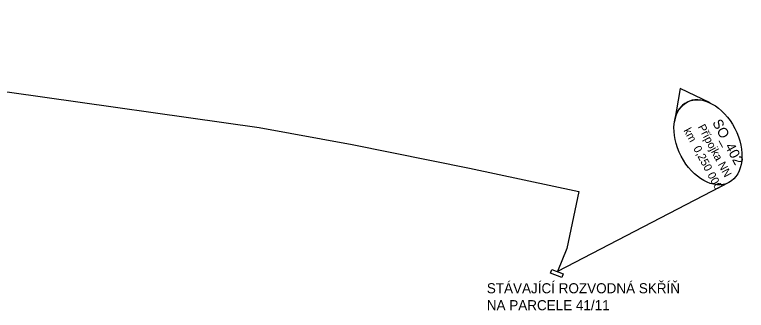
# Model space of a CAD drawing. Extents: x -743359 to -742769, y -1127804 to -1126284.
# Drawn here: x -743077.7 to -742896.2, y -1127156 to -1127082.6 of the extents above; entities that cross this region are included whole.
import ezdxf

# ---------------------------------------------------------------- set-up
doc = ezdxf.new("R2010")
doc.units = 0
for name, color, linetype in [('_Násyp', 7, 'Continuous'), ('_TRASA_vedení kabelu_CEZ', 7, 'Continuous'), ('bublina_růžová_230_čára_tenká', 7, 'Continuous'), ('bublina_růžová_230_čára_tučná', 7, 'Continuous')]:
    doc.layers.add(name, color=color, linetype=linetype)

msp = doc.modelspace()

# ---------------------------------------------------------------- linework, layer by layer
at = {"layer": '_TRASA_vedení kabelu_CEZ'}
msp.add_lwpolyline([(-743154.26, -1127082.61), (-743159.25, -1127091.79), (-743078.98, -1127101.9), (-743017.04, -1127110.61), (-742993.93, -1127114.82), (-742964.82, -1127120.76), (-742937.74, -1127126.54), (-742940.65, -1127140.7), (-742943, -1127146.4)], dxfattribs=at)
msp.add_lwpolyline([(-742944.4, -1127145.87), (-742941.59, -1127146.92), (-742941.94, -1127147.86), (-742944.75, -1127146.81)], close=True, dxfattribs=at)
at = {"layer": 'bublina_růžová_230_čára_tenká'}
msp.add_line((-742900.48, -1127124.28), (-742943, -1127146.4), dxfattribs=at)
at = {"layer": 'bublina_růžová_230_čára_tučná'}
for p, q in [((-742912.6, -1127100.99), (-742913.98, -1127109.13)), ((-742912.6, -1127100.99), (-742913.98, -1127109.13)), ((-742905.14, -1127104.53), (-742912.6, -1127100.99)), ((-742905.14, -1127104.53), (-742912.6, -1127100.99))]:
    msp.add_line(p, q, dxfattribs=at)
msp.add_ellipse((-742905.68, -1127114.3), major_axis=(5.19, -9.98), ratio=0.666667, dxfattribs=at)
msp.add_ellipse((-742905.68, -1127114.3), major_axis=(-5.19, 9.98), ratio=0.666473, start_param=5.557317, end_param=7.009053, dxfattribs=at)

# ---------------------------------------------------------------- texts
at = {"layer": '_Násyp'}
for s, height, p in [('Přípojka NN', 2, (-742908.27, -1127110.47)), ('SO_402', 2.5, (-742904.68, -1127109.39)), ('km  0,250 000', 2, (-742911.78, -1127111.35))]:
    msp.add_text(s, height=height, rotation=298.159, dxfattribs=at).set_placement(p)
at = {"layer": '_TRASA_vedení kabelu_CEZ'}
for s, p in [('STÁVAJÍCÍ ROZVODNÁ SKŘÍŇ ', (-742960.54, -1127151.78)), ('NA PARCELE 41/11', (-742960.54, -1127155.99))]:
    msp.add_text(s, height=2.5, dxfattribs=at).set_placement(p)

doc.saveas('drawing.dxf')
